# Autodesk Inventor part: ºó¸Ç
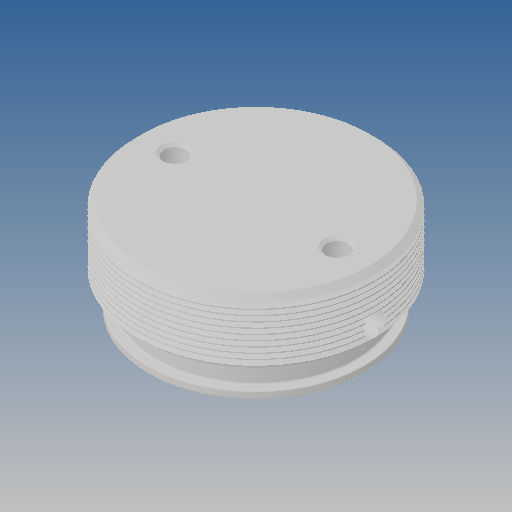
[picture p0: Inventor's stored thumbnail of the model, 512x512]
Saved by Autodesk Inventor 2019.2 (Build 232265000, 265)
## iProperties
Created: 2013-09
Part Number: ºó¸Ç
Material: Ogólny
Document SubType Name: Modeling
Designer: CADENGINEERING4
Density: 1 g/cm^3
Appearance: Domyślna
Author: CADENGINEERING4
Revision Number: ÈÎºÎ
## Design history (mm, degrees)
feature "µ¹½Ç1"
node "Bryła1"
